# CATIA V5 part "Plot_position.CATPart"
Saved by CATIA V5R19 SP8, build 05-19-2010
Part number: Plot_position
Revision: ANY
Definition: UNKNOWN
Nomenclature: 6
Source: Unknown
Bounding box of the stored display mesh (mm): x -11.5 to 11.5, y -11.5 to 0, z 0 to 10
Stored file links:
  D:\Documents\1_Travail\2- 2I2D\1 - Cours et TD\2- TD\3-TD Assemblage\Pompe AirMan\Plot_position.CATPart
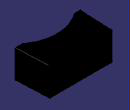
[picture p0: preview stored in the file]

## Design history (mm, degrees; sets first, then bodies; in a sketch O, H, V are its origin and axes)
Body1 "Congé1" (main body)
  Solid1: solid without history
